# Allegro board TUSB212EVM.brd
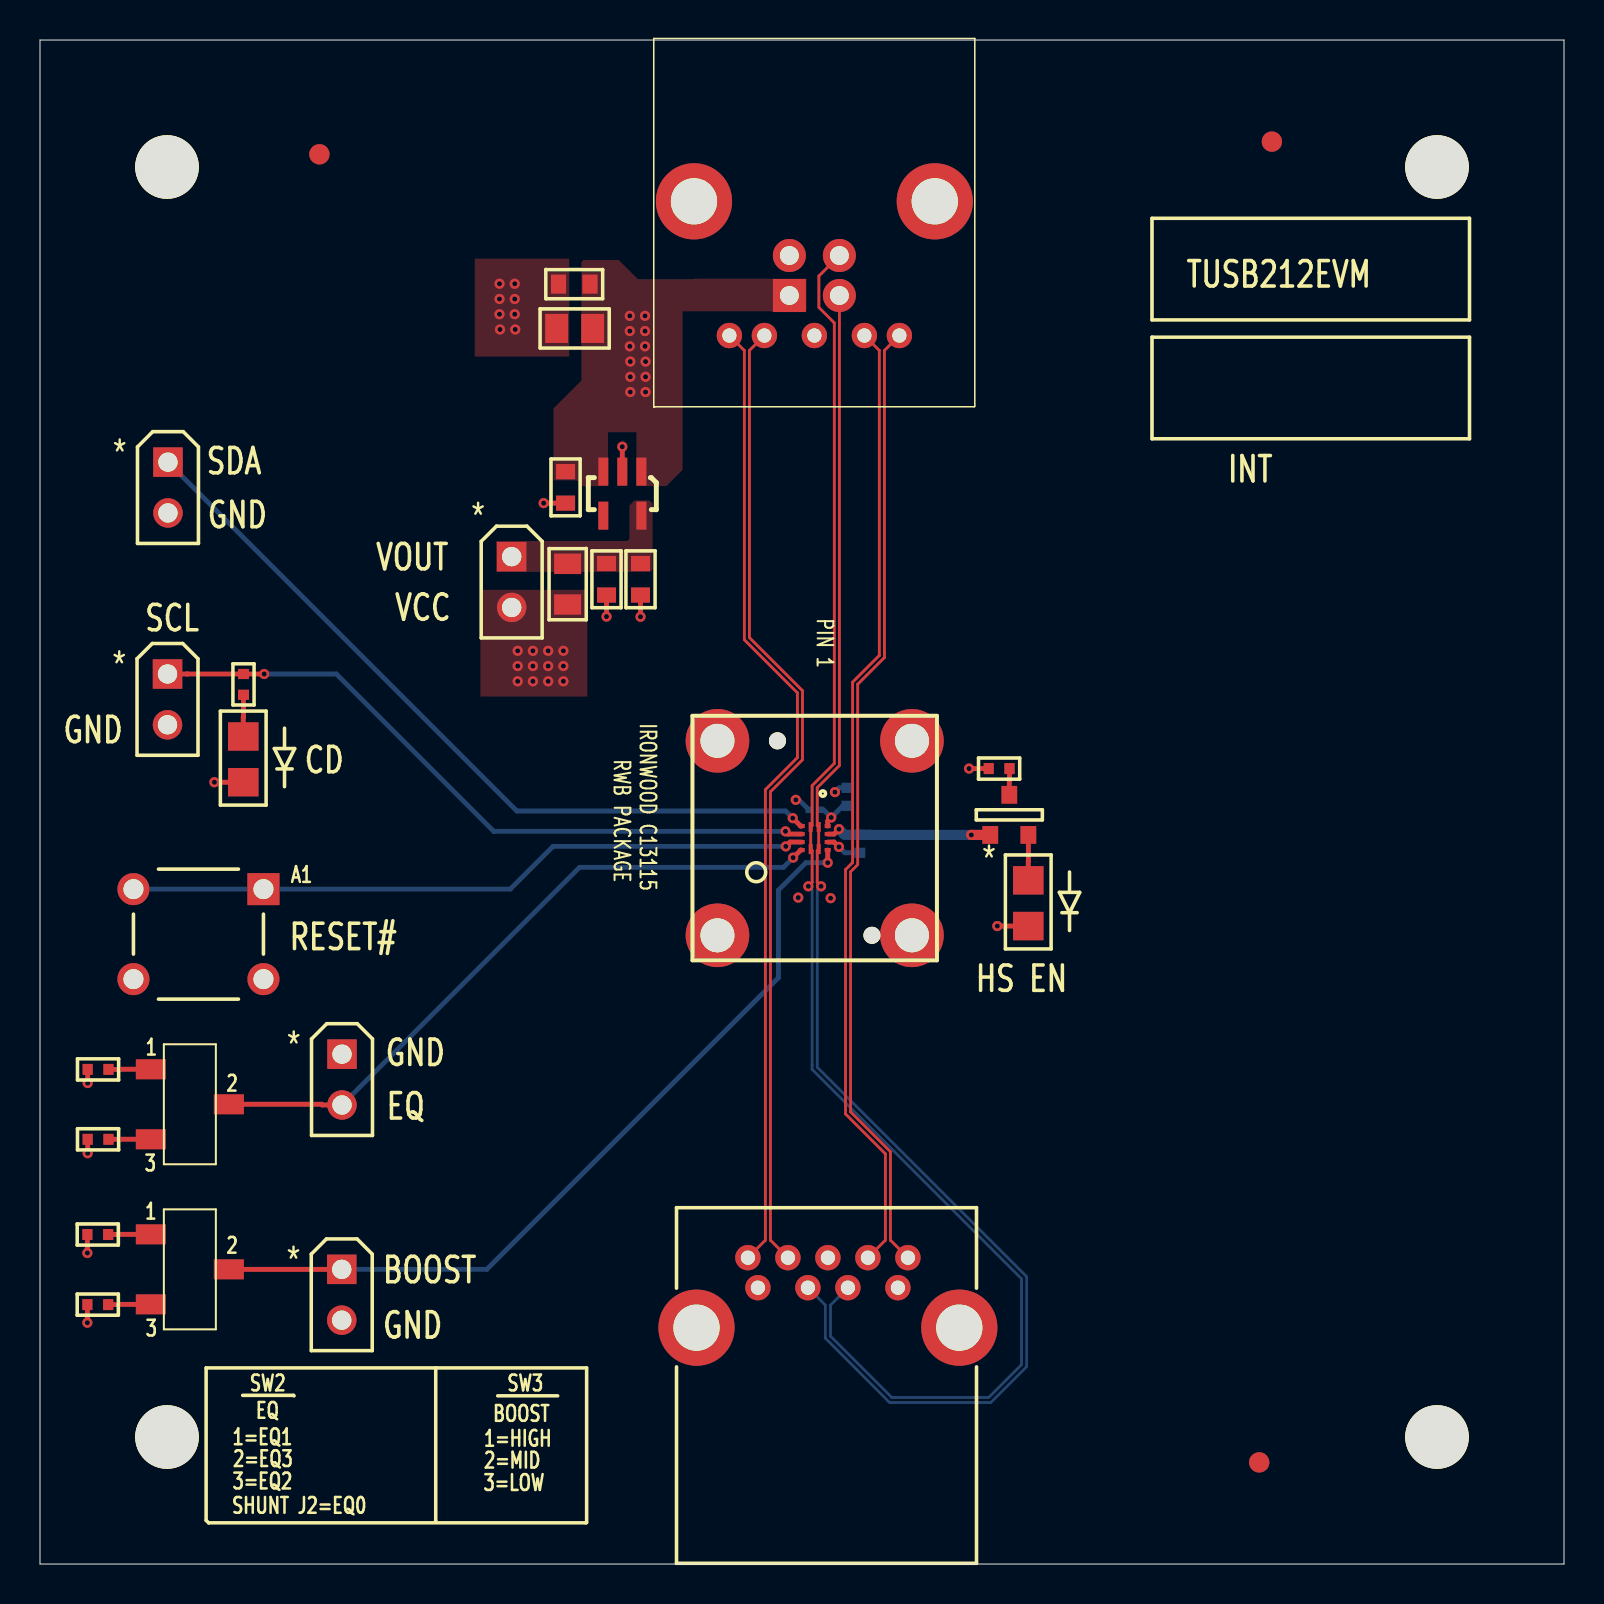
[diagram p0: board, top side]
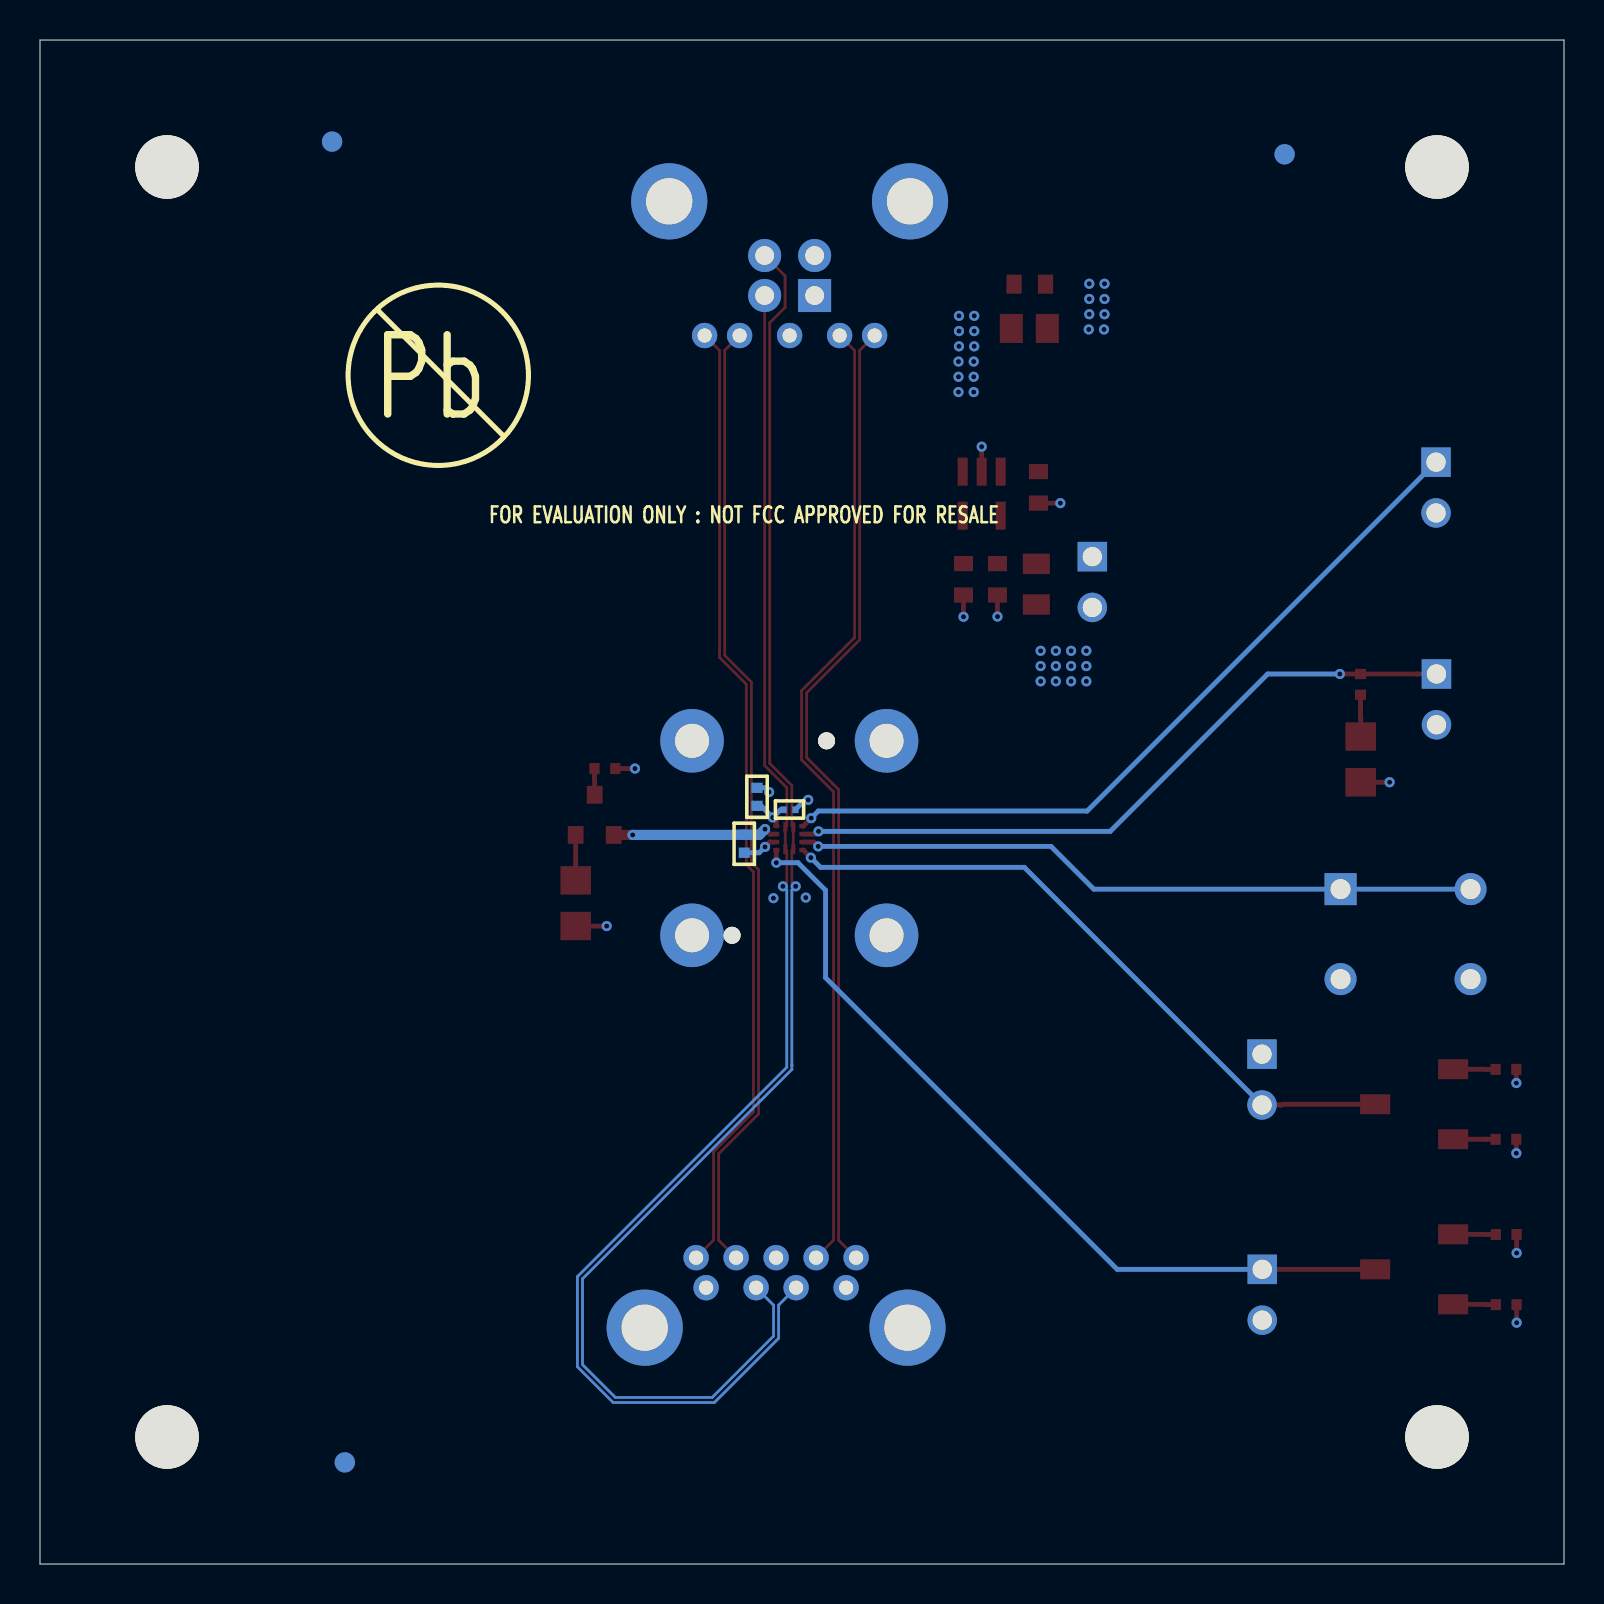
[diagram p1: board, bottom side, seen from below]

Outline 76.2 x 76.2 mm; copper layers: TOP, L2_GND, L3_PWR, BOTTOM. Coordinates in mm from the lower left corner of the outline.
Outline path: 0,76.2 76.2,76.2 76.2,0 0,0 0,76.2

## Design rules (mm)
net group DIFFPAIR0: nets SSTXN SSTXP
net group DIFFPAIR1: nets SSRXN SSRXP
net group DIFFPAIR2: nets DM DP

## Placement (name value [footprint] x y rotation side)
C1  10uF  [C0805]  26.73 61.78 180 top
C2  1uf  [C0603]  26.71 63.99 180 top
C3  1uf  [C0603]  26.28 53.83 270 top
C4  1uf  [C0603]  28.33 49.24 270 top
C5  1uf  [C0603]  30.03 49.24 270 top
C6  0.1uF  [C0402]  40.99 36.01 270 bottom
C7  0.1uF  [C0402]  40.35 38.36 90 bottom
C8  0.01uF  [C0201]  38.72 37.71 180 bottom
D1  LED Green 0805  [LED_0805]  49.41 33.04 90 top
D2  LED Green 0805  [LED_0805]  10.16 40.23 90 top
J1  HDR2X1 M .1  [HDR_THVT_1X2_100_M]  23.58 50.37 0 top
J2  HDR2X1 M .1  [HDR_THVT_1X2_100_M]  6.4 55.09 0 top
J3  HDR2X1 M .1  [HDR_THVT_1X2_100_M]  15.1 25.49 0 top
J4  HDR2X1 M .1  [HDR_THVT_1X2_100_M]  6.38 44.5 0 top
J5  HDR2X1 M .1  [HDR_THVT_1X2_100_M]  15.09 14.73 0 top
NOREF  -  [unnamed]  60.96 5.08 0 top
NOREF#2  -  [#2]  -3.81 -69.85 0 top
NOREF#3  -  [#2]  73.51 21.26 90 top
NOREF#4  -  [unnamed]  13.97 70.48 0 top
NOREF#5  -  [#2]  0 76.2 0 top
NOREF#6  -  [unnamed]  6.35 6.35 0 top
NOREF#7  -  [#2]  88.9 38.1 0 top
NOREF#8  -  [unnamed]  6.35 69.85 0 top
NOREF#9  -  [#2]  76.2 0 90 top
NOREF#10  -  [unnamed]  69.85 6.35 0 top
NOREF#11  -  [#2]  0 0 0 top
NOREF#12  -  [unnamed]  69.85 69.85 0 top
NOREF#13  -  [unnamed]  61.59 71.12 0 top
NOREF#14  -  [#2]  10.39 60.66 180 bottom
NOREF#15  -  [unnamed]  60.96 5.08 180 bottom
NOREF#16  -  [unnamed]  61.59 71.12 180 bottom
NOREF#17  -  [unnamed]  13.97 70.48 180 bottom
NOREF#18  -  [#2]  56.29 59.44 180 bottom
P1  USB3.0 Type B Receptacle  [USB3_TYPEB_AK4AA009]  37.47 63.42 180 top
P2  USB3 Type A Receptacle  [USB3_TYPEA]  39.4 15.32 0 top
Q1  NPN  [SOT_23_321]  48.47 37.46 0 top
R1  0  [R0805]  26.38 48.99 270 top
R2  75  [R0402]  47.96 39.77 0 top
R3  1.7K  [R0402]  2.9 24.73 0 top
R4  3.8K  [R0402]  2.9 21.23 0 top
R5  75  [R0402]  10.18 43.98 270 top
R6  15K  [R0402]  2.89 16.47 0 top
R7  15K  [R0402]  2.89 12.97 0 top
SW1  Switch - Push Button  [SW_THVT_EVQPAX04]  7.92 31.49 270 top
SW2  Switch CJS-1201  [CJS-1200B]  7.49 22.99 0 top
SW3  Switch CJS-1201  [CJS-1200B]  7.49 14.73 0 top
U1  TUSB212  [IRONWOOD_12PIN_C13115]  38.73 36.3 270 top
U2  LP5907  [DBV_R-PDSO-G5]  29.12 53.52 270 top

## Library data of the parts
C1 = cc0805
C2-C5 = cc0603 1.0uf 25V
C6 C7 = cc0402
C8 = cc0201
D1 D2 = LED Green 0805_0
J1-J5 = HDR2X1 M .1
P1 = USB 3.0 Type B Receptacle
P2 = USB 3.0 Type A Receptacle
Q1 = MMBT2222L
R1 = r0805
R2-R7 = r0402
SW1 = Switch - Push Button_0
SW2 SW3 = Switch CJS-1201
U1 = TUSB212RWB_0
U2 = LP5907

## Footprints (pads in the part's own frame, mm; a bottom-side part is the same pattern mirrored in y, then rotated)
C0201
  rect 0.3x0.33 smd: 1(-0.3,0) 2(0.3,0)
C0402
  rect 0.51x0.55 smd: 1(-0.45,0) 2(0.45,0)
C0603
  rect 0.76x0.95 smd: 1(-0.787,0) 2(0.787,0)
C0805
  rect 1.15x1.45 smd: 1(-0.9,0) 2(0.9,0)
CJS-1200B
  rect 1.5x1 smd: 1(-1.95,1.75) 2(1.95,0) 3(-1.95,-1.75)
DBV_R-PDSO-G5
  rect 1.4x0.5 smd: 1(-1.1,0.95) 2(-1.1,0) 3(-1.1,-0.95) 4(1.1,-0.95) 5(1.1,0.95)
HDR_THVT_1X2_100_M
  rect 1.473x1.473 hole 0.965: 1(0,0)
  round 1.473 hole 0.965: 2(0,-2.54)
IRONWOOD_12PIN_C13115
  round 3.18 hole 1.7: (-4.862,4.862) (-4.862,-4.862) (4.862,4.862) (4.862,-4.862)
  round 0.85 hole 0.85 unplated: (-4.862,-1.862) (4.862,2.862)
  rect 0.5x0.2 smd: 1(-0.55,0.2) 2(-0.55,-0.2) 7(0.55,-0.2) 8(0.55,0.2)
  rect 0.2x0.3 smd: 3(-0.6,-0.65) 4(-0.2,-0.65) 5(0.2,-0.65) 6(0.6,-0.65) 9(0.6,0.65) 10(0.2,0.65) 11(-0.2,0.65) 12(-0.6,0.65)
LED_0805
  rect 1.422x1.524 smd: 1(-1.143,0) 2(1.143,0)
R0402
  rect 0.51x0.55 smd: 1(-0.52,0) 2(0.52,0)
R0805
  rect 1.02x1.35 smd: 1(-1.016,0) 2(1.016,0)
SOT_23_321
  rect 0.787x0.889 smd: 1(-0.953,-1.003) 2(0.953,-1.003) 3(0,1.003)
SW_THVT_EVQPAX04
  rect 1.6x1.6 hole 1: A1(-2.25,3.25)
  round 1.6 hole 1: A2(-2.25,-3.25) B1(2.25,3.25) B2(2.25,-3.25)
unnamed
  round 1.016 smd: (0,0)
USB3_TYPEA
  round 1.27 hole 0.711: 1(-3.5,-1.5) 2(-1,-1.5) 3(1,-1.5) 4(3.5,-1.5) 5(4,0) 6(2,0) 7(0,0) 8(-2,0) 9(-4,0)
  round 3.81 hole 2.311: 10(-6.57,-3.5) 11(6.57,-3.5)
USB3_TYPEB_AK4AA009
  rect 1.651x1.651 hole 0.94: 1(0,0)
  round 1.651 hole 0.94: 2(-2.5,0) 3(-2.5,-2) 4(0,-2)
  round 1.27 hole 0.711: 5(-5.5,2) 6(-3.75,2) 7(-1.25,2) 8(1.25,2) 9(3,2)
  round 3.81 hole 2.311: 10(-7.27,-4.71) 11(4.77,-4.71)

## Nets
GND: C1.2 C2.2 C3.2 C4.2 C5.2 C6.2 C7.2 C8.2 D1.1(CATHODE) D2.1(CATHODE) J2.2 J3.1 J4.2 J5.2 P1.4(GND) P1.7(GND_DRAIN) P1.10(SHIELD1) P1.11(SHIELD2) P2.4(GND) P2.7(GND_DRAIN) P2.10(SHIELD1) P2.11(SHIELD2) R3.1 R4.1 R7.1 SW1.B1 SW1.B2 U1.10(GND) U2.2(GND)
VBUS: C1.1 C2.1 C3.1 P1.1(VBUS) P2.1(VBUS) U2.1(VIN) U2.3(EN)
VCC: C7.1 C8.1 J1.2 R1.2 R2.1 R6.1 U1.12(VCC)
BOOST: J5.1 SW3.2 U1.9(BOOST/EN_HS)
DM: P1.2(USB2_DM) P2.2(USB2_DM) U1.1(D1M) U1.8(D2M)
DP: P1.3(USB2_DP) P2.3(USB2_DP) U1.2(D1P) U1.7(D2P)
EQ: J3.2 SW2.2 U1.6(EQ)
RSTN: SW1.A1 SW1.A2 U1.5(RSTN)
SCL/CD: J4.1 R5.1 U1.4(SCL/CD)
SDA: J2.1 U1.3(SDA)
SSRXN: P1.8(SS_RX_N) P2.8(SS_TX_N)
SSRXP: P1.9(SS_RX_P) P2.9(SS_TX_P)
SSTXN: P1.5(SS_TX_N) P2.5(SS_RX_N)
SSTXP: P1.6(SS_TX_P) P2.6(SS_RX_P)
VREG: C6.1 Q1.1(B) U1.11(VREG)
N16640398: C4.1 C5.1 J1.1 R1.1 U2.5(VOUT)
N16640739: Q1.3(C) R2.2
N16641020: D1.2(ANNODE) Q1.2(E)
N16642054: R3.2 SW2.1
N16642058: R4.2 SW2.3
N16642695: D2.2(ANNODE) R5.2
N16643268: R6.2 SW3.1
N16643272: R7.2 SW3.3

Pads without a net: U2 4

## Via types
v1: diameter 0.508, hole 0.254, TOP to BOTTOM, 59 vias

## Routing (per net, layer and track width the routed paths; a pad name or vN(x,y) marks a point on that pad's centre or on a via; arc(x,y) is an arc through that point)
GND: length 80.9
  TOP w0.241: R4.1 v1(2.38,20.54) ; C5.2 v1(30.03,47.36) ; v1(39.95,35.85) 39.71,36.1 U1.10 ; D2.1 v1(8.72,39.09) ; C3.2 v1(25.18,53.04) ; D1.1 v1(47.87,31.9) ; U2.2 v1(29.12,55.86) ; R3.1 v1(2.38,24.05) ; R7.1 v1(2.37,12.07) ; C4.2 v1(28.33,47.37)
  L2_GND w0.241: J5.2 15.09,13.11 ; J5.2 16,12.19 ; J5.2 15.09,11.28 ; J5.2 14.17,12.19 ; 4.67,28.27 SW1.B2 ; SW1.B2 5.65,29.24 ; SW1.B2 4.67,30.22 ; SW1.B2 3.69,29.24 ; P2.10 34.91,11.82 ; P2.10 32.83,13.9 ; P2.10 30.74,11.82 ; P2.10 32.83,9.73 ; 5.46,41.96 J4.2 ; J4.2 7.29,41.96 ; J4.2 6.38,41.05 ; J4.2 6.38,42.88 ; J3.1 15.1,26.41 ; J3.1 16.02,25.49 ; J3.1 14.19,25.49 ; J3.1 15.1,24.58 ; P1.10 44.74,70.22 ; P1.10 44.74,66.05 ; P1.10 46.82,68.13 ; P1.10 42.66,68.13 ; P2.7 39.4,16.13 ; P2.7 38.58,15.32 ; P2.7 40.21,15.32 ; P2.7 39.4,14.5 ; 43.88,11.82 P2.11 ; P2.11 48.05,11.82 ; P2.11 45.97,13.9 ; P2.11 45.97,9.73 ; 32.7,66.05 P1.11 ; P1.11 30.62,68.13 ; P1.11 34.78,68.13 ; P1.11 32.7,70.22 ; 11.17,28.27 SW1.B1 ; SW1.B1 12.15,29.24 ; SW1.B1 10.19,29.24 ; SW1.B1 11.17,30.22 ; 6.4,51.64 J2.2 ; J2.2 6.4,53.47 ; J2.2 5.48,52.55 ; J2.2 7.31,52.55 ; 42.08,13.82 P2.4 ; P2.4 43.71,13.82 ; P2.4 42.9,13 ; P1.4 38.47,65.42 ; P1.4 36.47,65.42 ; P1.4 37.47,66.43 ; 38.72,60.61 P1.7 ; P1.7 37.91,61.42 ; P1.7 38.72,62.24 ; P1.7 39.53,61.42
  BOTTOM w0.241: v1(37.79,38.21) 37.94,38.21 38.42,37.73 C8.2 ; C7.2 39.96,38.81 v1(39.75,38.6) ; v1(39.95,35.85) 40.24,35.56 C6.2
  vias: v1(22.97,64.01) v1(22.97,63.25) v1(22.97,62.49) v1(23,61.73) v1(23.74,64.01) v1(23.74,63.25) v1(23.74,62.49) v1(23.76,61.73) v1(37.91,33.32) v1(39.53,33.29)
VBUS: length 2.4
  L3_PWR w0.241: 35.08,13.82 P2.1 ; P2.1 36.71,13.82 ; P2.1 35.9,13
  vias: v1(29.49,62.41) v1(29.49,61.65) v1(29.49,60.88) v1(29.51,60.12) v1(29.51,59.36) v1(29.51,58.6) v1(30.25,62.41) v1(30.25,61.65) v1(30.25,60.88) v1(30.28,60.12) v1(30.28,59.36) v1(30.28,58.6)
VCC: length 4.1
  TOP w0.241: U1.12 39.38,37.15 v1(39.56,37.33) ; R2.1 v1(46.45,39.77) ; R6.1 v1(2.37,15.55)
  BOTTOM w0.241: C7.1 40.14,37.91 v1(39.56,37.33) 39.17,37.71 C8.1
  vias: v1(23.88,45.66) v1(23.88,44.9) v1(23.88,44.14) v1(24.65,45.66) v1(24.65,44.9) v1(24.65,44.14) v1(25.41,45.66) v1(25.41,44.9) v1(25.41,44.14) v1(26.17,45.66) v1(26.17,44.9) v1(26.17,44.14)
BOOST: length 41.6
  TOP w0.241: SW3.2 J5.1 ; U1.9 v1(39.38,35.06)
  BOTTOM w0.241: v1(39.38,35.06) 38.3,35.06 36.92,33.69 36.92,29.31 22.34,14.73 J5.1
DM: length 73.6
  TOP w0.14: v1(39.05,33.88) 38.86,34.08 38.86,35.67 U1.8 U1.1 38.86,36.92 38.86,38.82 39.97,39.92 P1.2
  BOTTOM w0.14: P2.2 39.27,12.94 39.27,11.29 42.48,8.07 47.54,8.07 49.33,9.86 49.33,14.37 38.86,24.83 38.86,33.69 v1(39.05,33.88)
DP: length 75.5
  TOP w0.14: P1.3 38.94,64.4 38.94,62.83 39.72,62.06 39.72,40.03 38.61,38.92 38.61,36.92 U1.2 U1.7 38.61,35.67 38.61,34.08 v1(38.42,33.88)
  BOTTOM w0.14: v1(38.42,33.88) 38.61,33.69 38.61,24.94 38.61,24.73 49.08,14.26 49.08,9.97 47.43,8.33 42.59,8.33 39.52,11.39 39.52,12.94 P2.3
EQ: length 33.9
  TOP w0.241: J3.2 14.12,22.95 14.08,22.99 SW2.2 ; U1.6 38.03,35.7 v1(37.66,35.32)
  BOTTOM w0.241: J3.2 26.98,34.83 37.17,34.83 v1(37.66,35.32)
RSTN: length 34.4
  TOP w0.241: v1(37.29,35.88) 37.51,36.1 U1.5
  BOTTOM w0.241: SW1.A2 SW1.A1 23.51,33.74 25.65,35.88 v1(37.29,35.88)
SCL/CD: length 35
  TOP w0.241: J4.1 7.36,44.5 R5.1 v1(11.21,44.5) ; v1(37.27,36.63) 37.41,36.5 U1.4
  BOTTOM w0.241: v1(11.21,44.5) 14.82,44.5 22.69,36.63 v1(37.27,36.63)
SDA: length 39.2
  TOP w0.241: v1(37.64,37.29) 38.03,36.9 U1.3
  BOTTOM w0.241: J2.1 23.84,37.65 37.28,37.65 v1(37.64,37.29)
SSRXN: length 48.5
  TOP w0.14: P2.8 36.52,16.19 36.52,38.61 38.12,40.21 38.12,43.67 35.47,46.32 35.47,60.68 P1.8
SSRXP: length 48.5
  TOP w0.14: P1.9 35.22,60.68 35.22,46.21 37.87,43.56 37.87,40.32 36.27,38.72 36.27,16.19 P2.9
SSTXN: length 48.3
  TOP w0.14: P2.5 42.52,16.19 42.52,20.61 40.53,22.61 40.53,34.61 40.88,34.97 40.88,43.99 42.22,45.32 42.22,45.53 42.22,60.68 P1.5
SSTXP: length 48.3
  TOP w0.14: P1.6 41.97,60.68 41.97,45.43 40.63,44.09 40.63,35.07 40.27,34.72 40.27,22.5 42.27,20.51 42.27,16.19 P2.6
VREG: length 8.4
  TOP w0.241: v1(39.95,36.74) 39.95,36.74 39.71,36.5 U1.11
  TOP w0.508: Q1.1 v1(46.57,36.45)
  BOTTOM w0.508: v1(46.57,36.45) 41.52,36.45 41.51,36.46 C6.1 40.23,36.46 v1(39.95,36.74)
N16640739: length 1.3
  TOP w0.241: Q1.3 48.47,39.15 48.48,39.16 R2.2
N16641020: length 2.3
  TOP w0.241: Q1.2 49.42,35.15 49.41,35.14 D1.2
N16642054: length 2.1
  TOP w0.241: R3.2 3.93,24.73 3.93,24.74 SW2.1
N16642058: length 2.1
  TOP w0.241: R4.2 3.93,21.23 3.93,21.24 SW2.3
N16642695: length 2.1
  TOP w0.241: R5.2 10.18,42.35 10.16,42.33 D2.2
N16643268: length 2.1
  TOP w0.241: R6.2 3.91,16.47 3.92,16.48 SW3.1
N16643272: length 2.1
  TOP w0.241: R7.2 3.91,12.97 3.92,12.98 SW3.3

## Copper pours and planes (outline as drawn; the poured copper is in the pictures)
GND on TOP: 26.46,60.37 26.46,65.27 21.74,65.27 21.74,60.37
GND on L2_GND: 0.51,0.51 0.51,75.69 75.69,75.69 75.69,0.51
VBUS on TOP: 38.33,62.56 38.33,64.26 32.66,64.26 32.64,64.24 29.9,64.24 28.93,65.2 27.18,65.2 27.08,65.1 27.08,59.18 25.66,57.77 25.66,54.16 25.69,54.19 26.83,54.19 27.12,53.9 28.39,53.9 28.39,56.57 28.42,56.59 29.82,56.59 29.82,53.9 31.31,53.9 32.13,54.72 32.13,62.64 38.25,62.64
VBUS on L3_PWR: 0.51,0.51 0.51,10.53 6.74,10.53 6.88,10.39 7.09,10.39 7.24,10.54 7.24,44.11 5.48,45.87 5.48,56.25 6.77,57.54 15.3,57.54 19.82,53.02 19.82,44.65 23.12,41.35 29.9,41.35 29.95,41.39 33.66,41.39 38.42,36.62 41.74,36.62 43.89,38.78 47.77,38.78 47.77,45.13 43.74,49.16 25.42,49.16 25.42,50.89 25.51,50.98 25.51,75.69 75.69,75.69 75.69,0.51
VCC on TOP: 22.03,48.7 22.03,43.37 27.37,43.37 27.37,48.7
VCC on L3_PWR: 0.51,11.04 0.51,75.69 25.01,75.69 25.01,51.19 24.91,51.1 24.91,48.66 43.53,48.66 47.26,44.92 47.26,39.28 43.68,39.28 41.53,37.13 38.63,37.13 33.87,41.9 29.73,41.9 29.69,41.85 23.33,41.85 20.3,44.88 20.3,53.25 15.51,58.05 6.55,58.05 4.97,56.47 4.97,45.66 6.73,43.9 6.73,11.04
N16640398 on TOP: 22.83,49.61 30.51,49.61 30.63,49.73 30.63,53.02 30.48,53.17 29.71,53.17 29.47,52.93 29.47,51.25 29.37,51.15 22.81,51.15 22.81,49.63

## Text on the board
BOTTOM: LAYER 4 - BOTTOM SIDE
Board Geometry/Soldermask Bottom: SOLDERMASK BOTTOM
Package Geometry/Pastemask Bottom: PASTEMASK BOTTOM
Ref Des/Silkscreen Bottom: FOR EVALUATION ONLY : NOT FCC APPROVED FOR RESALE | SILKSCREEN BOTTOM
TOP: LAYER 1 - TOP SIDE
Board Geometry/Soldermask Top: SOLDERMASK TOP
Package Geometry/Pastemask Top: PASTEMASK TOP
Ref Des/Silkscreen Top: 3 | 1 | 2 | SHUNT J2=EQ0 | 1=EQ1 | 3=EQ2 | 2=EQ3 | SW2 | EQ | 3=LOW | 1=HIGH | 2=MID | BOOST | SW3 | GND | SCL | SDA | RESET# | CD | VOUT | VCC | HS EN | TUSB212EVM | INT | SILKSCREEN TOP
L2_GND: LAYER 2 - GND PLANE
L3_PWR: LAYER 3 - PWR PLANE
XSECTION_CHART: * AIR 0 MIL | * SOLDERMASK-0.8MIL 0.8 MIL | L1: COPPER_1/2OZ_PLATED 1.4 MIL | * FILL_0.150 5.91 MIL | L2: COPPER_1.0OZ 1.4 MIL | * CORE_1.10 43.31 MIL | L3: COPPER_1.0OZ 1.4 MIL | L4: COPPER_1/2OZ_PLATED 1.4 MIL | DESIGN CROSS SECTION CHART | ___________________________ | TOTAL THICKNESS 62.33 MIL | 1-4
DIMENSION: FABRICATION DRAWING | CAD ORIGIN
User.6: LAYER 1 | LAYER 2 | LAYER 3 | LAYER 4 | LAYER | NO. | TABLE 1: | TOP | L2_GND | L3_PWR | BOTTOM | NAME | DIFFIRENTIAL PAIR | IMPEDANCE (OHMS) | 90  +/- 10% | DIFF TRACE | WIDTH | 0.0055" | SPACING | 0.0045" | SINGLE ENDED | 50 +/- 10% | TRACE WIDTH | 0.0095" | REFERENCE | SPECIAL FAB NOTES: | PLACE DRILL CHART HERE: | 1:FAB SHOP MUST FOLLOW THE SOLDER MASK REVIEW LAYERS. | 2: | MIN. ANNULAR RING 2 MIL EXTERNAL PER IPC-6012C CLASS 2 | REGISTRATION TOLERANCES: METAL +/- X MIL,HOLES +/- X MIL | IMPEDANCE CONTROL: | BOARD SIZE (REFER ALSO ARRAY/PANEL PROFILING INFORMATION) | MIXED DIELECTRIC: | LAMINATE MATERIAL: | THICKNESS: | TOLERANCE: | COPPER THICKNESS (FINISHED): | BOARD FINISH: | NUMBER OF LAYERS: | MIN. TRACK WIDTH: | MIN. CLEARANCE  : | MIN. VIA PAD/DRILL: | THIEVING ALLOWED: | X | OUTER: | INNER SIGNAL: | INNER PLANE: | OTHER: | SILKSCREEN: | SOLDERMASK: (PER IPC-6011,6012) | BOARD SURFACE TREATMENT: | ADDITIONAL REQUIREMENTS: | VENDOR MARKING: | SILKSCREEN COLOR: | SOLDERMASK COLOR: | THROUGH-HOLE VIA TREATMENT: | VIA FILL USING NON-CONDUCTIVE EPOXY: | FOR WIRE BONDING: | VENDOR DATE CODE,UL,LOGO: | FR-4 HIGH Tg | 0.062" +/-10% | IPC-6012C TYPE 3 CLASS 2 | OTHER +/- | MICRO-SECTION | CERTIFICATES OF COMPLIANCE | NICKEL/GOLD (ENIG) | IMMERSION TIN | HARD GOLD | IN AN OPEN AREA | 1/4 OZ. | OPEN | NO | 4 | 5.5 MIL | 4.5 MIL | 20/10 MIL | NONE | DESIGN INFORMATION | ROGERS 4350B | 0.093" +/-10% | YES | TDR REPORTS/COUPONS | WHITE | GREEN | SOFT GOLD | TENTED | 1/2 OZ. | BOW & TWIST: | ORGANIC (OSP) | OTHER | WHERE INDICATED (SEE DRAWING) | YES - SEE TABLE 1 | ETCH | IDENTIFIER: | BLUE | RoHS | 1.0 OZ. | SILKSCREEN | PER SUPPLIED ARTWORK | ALL 10 MIL VIAS | ALL x MIL VIAS | ELECTRICAL TEST | UL 94V-0 | HASL | 2.0 OZ. | BREAK-AWAY | ENEPIG
User.10: FIGURE | SIZE | 91.0 | 66.93 | 39.37 | 38.0 | 37.0 | 28.0 | 10.0 | 125.0 | 33.46 | DRILL CHART: TOP to BOTTOM | ALL UNITS ARE IN MILS | TOLERANCE | +3.0/-3.0 | +3.94/-0.0 | +2.0/-2.0 | PLATED | NON-PLATED | QTY | 4 | 10 | 14 | 59 | 2
